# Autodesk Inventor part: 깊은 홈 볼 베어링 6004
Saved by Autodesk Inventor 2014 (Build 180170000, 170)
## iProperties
Created: 2025-12
Part Number: 깊은 홈 볼 베어링 6004
Material: 일반
Document SubType Name: Modeling
Designer: dg
Density: 1 g/cm^3
Appearance: 기본값
Author: dg
Author: jhkim
Description: 깊은 그루브 볼 베어링
Creation Date: 2025-11-19
Sending System: Autodesk Inventor 2026
Preprocessor: ST-DEVELOPER v20.1
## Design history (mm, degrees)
node "깊은 홈 볼 베어링 60041"
body "Solid1"
node "Solid1_1"
node "Solid1_2"
node "Solid1_3"
node "Solid1_4"
node "Solid1_5"
node "Solid1_6"
node "Solid1_7"
node "Solid1_8"
node "Solid1_9"
node "Solid1_10"
node "기준1"
node "기준2"
node "기준3"
node "기준4"
node "기준5"
node "기준6"
node "기준7"
node "기준8"
node "기준9"
node "기준10"
node "기준11"
